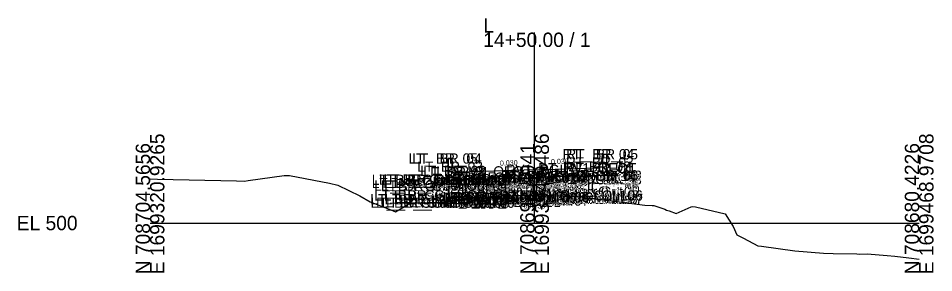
# Model space of a CAD drawing. Extents: x -63 to 1153, y -24 to 9522.
# Drawn here: x -25.7 to 152.8, y 5490.3 to 5540 of the extents above; entities that cross this region are included whole.
import ezdxf

# ---------------------------------------------------------------- set-up
doc = ezdxf.new("R2010")
doc.units = 0
for name, color, linetype in [('Default', 7, 'Continuous'), ('Exist Cross Section Cell', 7, 'Continuous'), ('Exist XS Center Line Elevation Label', 7, 'Continuous'), ('Exist XS Ground Line', 7, 'Continuous'), ('Prop CMT Concrete Structures', 7, 'Continuous'), ('Prop CMT DNC', 7, 'Continuous'), ('Prop XS SE Text', 7, 'Continuous')]:
    doc.layers.add(name, color=color, linetype=linetype)

msp = doc.modelspace()

# ---------------------------------------------------------------- linework, layer by layer
at = {"layer": 'Exist Cross Section Cell'}
for p, q in [((75, 5500), (75, 5537.17)), ((0, 5500), (75, 5500)), ((75, 5500), (150, 5500))]:
    msp.add_line(p, q, dxfattribs=at)
at = {"layer": 'Exist XS Ground Line'}
msp.add_lwpolyline([(0, 5508.64), (1.47, 5508.55), (16.86, 5508.25), (18.41, 5508.16), (19.14, 5508.29), (26.15, 5509.29), (27.22, 5509.31), (34.98, 5507.77), (36.65, 5507.42), (40.91, 5505.28), (42.95, 5504.12), (46.66, 5502.73), (47.88, 5502.17), (49.94, 5503.45), (50.65, 5503.86), (50.72, 5503.91), (50.99, 5503.93), (57.04, 5504.07), (61.06, 5504.82), (62.37, 5505.02), (63.7, 5505.08), (72.85, 5505.43), (75, 5505.38), (83.36, 5505.21), (83.38, 5505.21), (83.39, 5505.21), (83.4, 5505.21), (83.4, 5505.21), (83.4, 5505.21), (83.41, 5505.21), (96.49, 5503.48), (97.91, 5503.44), (97.96, 5503.44), (98.28, 5503.44), (100.38, 5502.7), (100.75, 5502.5), (101.22, 5502.38), (102.6, 5501.87), (105.55, 5503.14), (105.89, 5503.23), (106.39, 5503.16), (112.2, 5501.83), (113.76, 5499.33), (114.43, 5497.73), (115.72, 5497.05), (118.55, 5495.52), (119.26, 5495.51), (125.73, 5494.58), (131.34, 5494.1), (133.21, 5494.06), (137.87, 5493.99), (138.44, 5493.95), (139.86, 5493.98), (143.78, 5493.65), (145.25, 5493.51), (147.97, 5493.21), (150, 5492.98)], dxfattribs=at)
at = {"layer": 'Prop CMT Concrete Structures'}
for points in [[(75, 5510.39), (85, 5510.69), (87.5, 5510.76), (87.51, 5511.01), (88.1, 5511.85), (88.26, 5513.43), (89, 5513.43), (89, 5509.31)], [(75, 5510.39), (65.06, 5510.09), (59.66, 5509.93), (59.65, 5510.18), (59.07, 5511.01), (58.9, 5512.6), (58.16, 5512.6), (58.16, 5508.38)], [(75, 5508.89), (75, 5510.39)], [(75, 5508.89), (75, 5510.39)], [(58.16, 5508.38), (65.06, 5508.59), (75, 5508.89)], [(62.12, 5508.5), (61.29, 5508.48), (60.46, 5508.45)], [(60.46, 5508.45), (60.46, 5507.81)], [(60.46, 5507.81), (60.96, 5507.31)], [(61.62, 5507.31), (62.12, 5507.81)], [(62.12, 5507.81), (62.12, 5508.5)], [(75, 5508.89), (74.17, 5508.86)], [(74.17, 5508.86), (74.17, 5508.22)], [(74.17, 5508.22), (74.67, 5507.72)], [(89, 5509.31), (85, 5509.19), (75, 5508.89)], [(75, 5508.89), (75.83, 5508.91)], [(75, 5504.39), (75, 5508.89)], [(75, 5504.39), (75, 5508.89)], [(75.83, 5508.22), (75.33, 5507.72)], [(75.83, 5508.91), (75.83, 5508.22)], [(85.05, 5509.19), (85.88, 5509.22), (86.71, 5509.24)], [(85.05, 5508.55), (85.05, 5509.19)], [(85.55, 5508.05), (85.05, 5508.55)], [(85.55, 5506.13), (85.55, 5508.05)], [(86.71, 5508.55), (86.21, 5508.05)], [(86.21, 5508.05), (86.21, 5506.13)], [(86.71, 5509.24), (86.71, 5508.55)], [(60.96, 5507.31), (60.96, 5505.39)], [(61.62, 5505.39), (61.62, 5507.31)], [(74.67, 5507.72), (74.67, 5505.81)], [(75.33, 5507.72), (75.33, 5505.81)], [(84.8, 5505.38), (85.55, 5506.13)], [(86.21, 5506.13), (86.96, 5505.38)], [(60.96, 5505.39), (60.21, 5504.64)], [(60.21, 5504.64), (60.21, 5503.98)], [(62.37, 5504.64), (61.62, 5505.39)], [(62.37, 5503.98), (62.37, 5504.64)], [(74.67, 5505.81), (73.92, 5505.06)], [(73.92, 5505.06), (73.92, 5504.39)], [(73.92, 5504.39), (75, 5504.39)], [(76.08, 5504.39), (75, 5504.39)], [(75.33, 5505.81), (76.08, 5505.06)], [(76.08, 5505.06), (76.08, 5504.39)], [(84.8, 5504.72), (84.8, 5505.38)], [(86.96, 5504.72), (85.88, 5504.72), (84.8, 5504.72)], [(86.96, 5505.38), (86.96, 5504.72)], [(60.21, 5503.98), (61.29, 5503.98), (62.37, 5503.98)]]:
    msp.add_lwpolyline(points, dxfattribs=at)

# ---------------------------------------------------------------- texts
at = {"layer": 'Default'}
msp.add_text('-', height=0.0001, dxfattribs=at).set_placement((0, 5500))
at = {"layer": 'Exist Cross Section Cell'}
for s, p in [('L', (65, 5537.17)), ('14+50.00 / 1', (65, 5534.37)), ('EL 500', (-26, 5498.6))]:
    msp.add_text(s, height=2.8, dxfattribs=at).set_placement(p)
for s, p in [('E 1699320.9265', (2.8, 5490)), ('E 1699394.9486', (77.8, 5490)), ('E 1699468.9708', (152.8, 5490)), ('N 708704.5656', (0, 5490)), ('N 708692.4941', (75, 5490)), ('N 708680.4226', (150, 5490))]:
    msp.add_text(s, height=2.8, rotation=90, dxfattribs=at).set_placement(p)
at = {"layer": 'Exist XS Center Line Elevation Label'}
msp.add_text('505.38', height=1, dxfattribs=at).set_placement((72.86, 5502.85))
at = {"layer": 'Prop CMT DNC'}
for s, p in [('LT_ BR_05', (50.4, 5511.6)), ('LT_ BR_04', (51.14, 5511.6)), ('RT_ BR_04', (80.45, 5512.43)), ('RT_ BR_05', (81.19, 5512.43)), ('LT_BR_03', (52.13, 5510.01)), ('PV1_PGL', (69.47, 5509.39)), ('RT_PV1_OEOT', (75.69, 5509.69)), ('RT_BR_02', (80.52, 5510.01)), ('RT_BR_01', (81.08, 5509.76)), ('RT_BR_03', (81.1, 5510.85)), ('LT_BR_Girder Out 02', (43.24, 5507.45)), ('LT_BR_Girder Out 01', (44.64, 5507.48)), ('LT_BR_Girder Out 14', (45.55, 5507.5)), ('LT_BR_02', (52.71, 5509.18)), ('LT_BR_01', (53.29, 5508.93)), ('LT_PV1_OEOT', (55.8, 5509.09)), ('LT_BR_Girder Mid 02', (57.35, 5507.86)), ('LT_BR_07', (58.11, 5507.59)), ('RT_BR_Girder Mid 02', (58.97, 5507.91)), ('RT_BR_Girder Out 14', (68.43, 5508.19)), ('RT_BR_Girder Out 13', (68.43, 5507.55)), ('RT_BR_Girder Out 01', (69.19, 5508.22)), ('RT_BR_Girder Out 02', (69.45, 5508.24)), ('RT_BR_Girder Out 03', (69.45, 5507.55)), ('BR_PGL', (69.83, 5507.89)), ('RT_BR_07', (78.01, 5508.19)), ('RT_BR_06', (81.97, 5508.31)), ('LT_BR_Girder Out 03', (43.24, 5506.81)), ('LT_BR_Girder Out 04', (43.74, 5506.31)), ('LT_BR_Girder Out 12', (45.05, 5506.31)), ('LT_BR_Girder Out 13', (45.55, 5506.81)), ('LT_BR_06', (51.17, 5507.38)), ('LT_BR_Girder Mid 03', (57.35, 5507.22)), ('LT_BR_Girder Mid 04', (57.85, 5506.72)), ('RT_BR_Girder Mid 04', (58.47, 5506.72)), ('RT_BR_Girder Mid 03', (58.97, 5507.22)), ('RT_BR_Girder Out 12', (68.93, 5507.05)), ('RT_BR_Girder Out 04', (68.95, 5507.05)), ('LT_BR_Girder Out 05', (43.74, 5504.39)), ('LT_BR_Girder Out 11', (45.62, 5504.39)), ('LT_BR_Girder Mid 06', (57.05, 5504.06)), ('LT_BR_Girder Mid 05', (57.85, 5504.81)), ('RT_BR_Girder Mid 05', (58.47, 5504.81)), ('RT_BR_Girder Mid 06', (59.17, 5504.06)), ('RT_BR_Girder Out 10', (68.1, 5504.38)), ('RT_BR_Girder Out 05', (68.95, 5505.13)), ('RT_BR_Girder Out 11', (69.5, 5505.13)), ('RT_BR_Girder Out 06', (69.66, 5504.38)), ('LT_BR_Girder Out 06', (42.95, 5503.64)), ('LT_BR_Girder Out 07', (42.99, 5502.98)), ('LT_BR_Girder Out 08', (44.08, 5502.98)), ('LT_BR_Girder Out 09', (45.16, 5502.98)), ('LT_BR_Girder Out 10', (45.73, 5503.64)), ('LT_BR_Girder Mid 07', (57.1, 5503.39)), ('RT_BR_Girder Mid 07', (59.22, 5503.39)), ('BR_Girder Mid 08', (60.87, 5503.39)), ('RT_BR_Girder Out 09', (67.54, 5503.72)), ('RT_BR_Girder Out 08', (68.62, 5503.72)), ('RT_BR_Girder Out 07', (69.7, 5503.72))]:
    msp.add_text(s, height=2, dxfattribs=at).set_placement(p)
at = {"layer": 'Prop XS SE Text'}
for p in [(68.25, 5511.19), (78.22, 5511.49)]:
    msp.add_text('0.030', height=1, rotation=1.7184, dxfattribs=at).set_placement(p)

doc.saveas('drawing.dxf')
